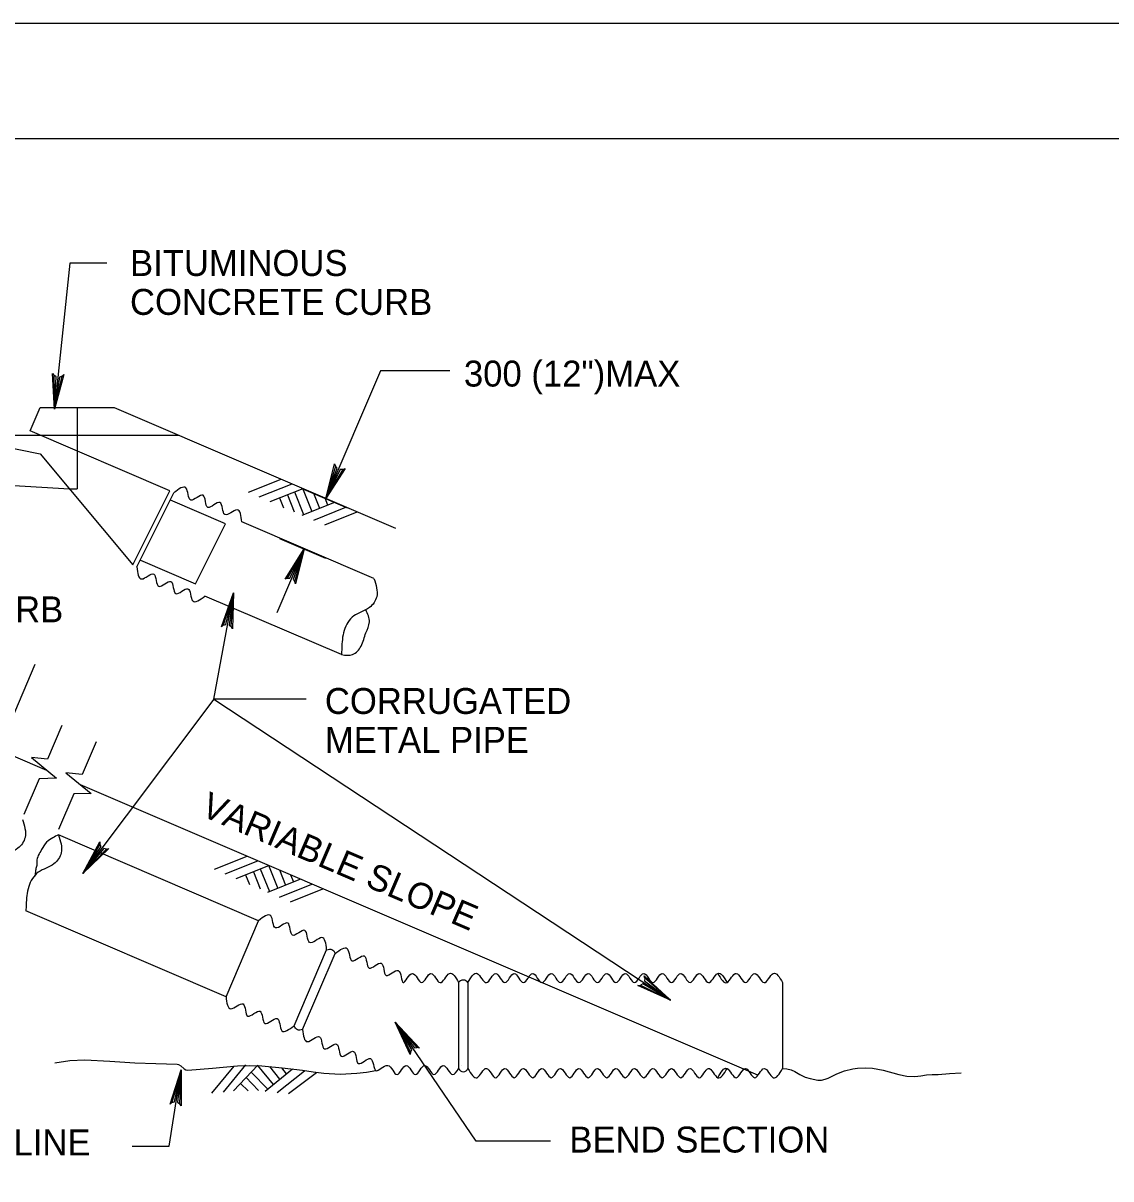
# Model space of a CAD drawing. Extents: x 637898 to 638802, y 298167 to 298761.
# Drawn here: x 638068.2 to 638209.3, y 298611.1 to 298760.9 of the extents above; entities that cross this region are included whole.
import ezdxf

# ---------------------------------------------------------------- set-up
doc = ezdxf.new("R2010")
doc.units = 0
for name, color, linetype in [('1', 7, 'Continuous'), ('2', 7, 'Continuous'), ('3', 7, 'Continuous'), ('PLT-BNDY', 7, 'Continuous')]:
    doc.layers.add(name, color=color, linetype=linetype)

msp = doc.modelspace()

# ---------------------------------------------------------------- linework, layer by layer
at = {"layer": '1'}
msp.add_lwpolyline([(638722.97, 298181.88), (638722.97, 298745.88), (637936.97, 298745.88), (637936.97, 298181.88), (638722.97, 298181.88), (638722.97, 298208.24), (638522.97, 298208.24), (638522.97, 298272.92), (638722.97, 298272.92), (638722.97, 298301.88), (638522.97, 298301.88), (638522.97, 298181.88), (638601.78, 298181.88), (638601.78, 298208.24), (638601.78, 298181.88), (638678.78, 298181.88), (638678.78, 298208.24), (638678.78, 298195.92), (638722.97, 298195.92)], dxfattribs=at)
at = {"layer": '2'}
for p, q in [((638114.56, 298715.8), (638107.47, 298699.26)), ((638069.11, 298708.04), (638070.42, 298711.08)), ((638070.42, 298711.08), (638080.02, 298711.08)), ((638075.22, 298711.08), (638075.22, 298707.48)), ((638058.42, 298707.48), (638070.42, 298705.08)), ((638087.22, 298700.28), (638069.11, 298708.04)), ((638075.22, 298707.48), (638075.22, 298700.52)), ((638070.42, 298705.08), (638082.42, 298690.68)), ((638039.61, 298702.6), (638074.22, 298700.52)), ((638097.45, 298700.08), (638101.67, 298701.76)), ((638098.83, 298699.48), (638103.08, 298701.18)), ((638074.22, 298700.52), (638075.22, 298700.52)), ((638082.42, 298690.68), (638087.22, 298700.28)), ((638082.95, 298690.41), (638087.76, 298700.01)), ((638087.76, 298700.01), (638087.76, 298700.01)), ((638100.26, 298698.87), (638104.51, 298700.57)), ((638101.46, 298699.35), (638101.97, 298698.08)), ((638102.49, 298699.76), (638103.38, 298697.54)), ((638103.4, 298700.12), (638104.57, 298697.2)), ((638104.27, 298700.63), (638110.23, 298698.08)), ((638104.44, 298700.6), (638105.64, 298697.6)), ((638105.87, 298699.98), (638106.65, 298698.03)), ((638107.32, 298699.36), (638107.69, 298698.43)), ((638089.96, 298699.07), (638089.96, 298699.07)), ((638089.96, 298699.07), (638089.96, 298699.07)), ((638092.17, 298698.12), (638092.17, 298698.12)), ((638092.17, 298698.12), (638092.17, 298698.12)), ((638104.38, 298697.11), (638108.64, 298698.81)), ((638105.89, 298696.46), (638110.08, 298698.14)), ((638094.37, 298697.18), (638094.37, 298697.18)), ((638107.32, 298695.85), (638111.51, 298697.53)), ((638096.58, 298696.23), (638096.58, 298696.23)), ((638113.71, 298688.89), (638096.58, 298696.23)), ((638098.79, 298695.29), (638098.79, 298695.29)), ((638100.99, 298694.34), (638100.99, 298694.34)), ((638101.46, 298694.1), (638107.43, 298691.54)), ((638103.2, 298693.4), (638103.2, 298693.4)), ((638105.4, 298692.45), (638105.4, 298692.45)), ((638082.95, 298690.41), (638082.95, 298690.41)), ((638107.61, 298691.51), (638107.61, 298691.51)), ((638109.82, 298690.56), (638109.82, 298690.56)), ((638112.02, 298689.62), (638112.02, 298689.62)), ((638089.57, 298687.58), (638089.57, 298687.58)), ((638091.78, 298686.63), (638091.78, 298686.63)), ((638109.49, 298679.04), (638091.78, 298686.63)), ((638093.98, 298685.69), (638093.98, 298685.69)), ((638096.19, 298684.74), (638096.19, 298684.74)), ((638098.4, 298683.8), (638098.4, 298683.8)), ((638100.6, 298682.85), (638100.6, 298682.85)), ((638102.81, 298681.91), (638102.81, 298681.91)), ((638105.02, 298680.96), (638105.02, 298680.96)), ((638107.22, 298680.02), (638107.22, 298680.02)), ((638109.43, 298679.07), (638109.43, 298679.07)), ((638069.71, 298677.75), (638065, 298666.74)), ((638073.24, 298669.86), (638071.36, 298665.47)), ((638077.67, 298667.74), (638075.85, 298663.5)), ((638070.29, 298662.96), (638068.31, 298658.34)), ((638074.78, 298660.99), (638072.79, 298656.36)), ((638098.74, 298644.56), (638072.79, 298655.69)), ((638093.03, 298651.23), (638097.25, 298652.92)), ((638094.41, 298650.64), (638098.66, 298652.33)), ((638095.84, 298650.02), (638100.08, 298651.72)), ((638100.02, 298651.75), (638101.22, 298648.75)), ((638097.05, 298650.5), (638097.55, 298649.23)), ((638098.07, 298650.91), (638098.95, 298648.69)), ((638098.97, 298651.28), (638100.15, 298648.35)), ((638099.95, 298648.26), (638104.22, 298649.97)), ((638101.45, 298651.14), (638102.23, 298649.18)), ((638102.9, 298650.52), (638103.27, 298649.59)), ((638101.46, 298647.61), (638105.66, 298649.29)), ((638102.89, 298647), (638107.09, 298648.68)), ((638094.52, 298634.71), (638068.57, 298645.84)), ((638094.52, 298634.71), (638098.74, 298644.56)), ((638103.34, 298630.93), (638107.57, 298640.78)), ((638104.45, 298630.46), (638108.67, 298640.31)), ((638108.67, 298640.31), (638108.67, 298640.31)), ((638110.88, 298639.36), (638110.88, 298639.36)), ((638113.08, 298638.42), (638113.08, 298638.42)), ((638115.29, 298637.47), (638115.29, 298637.47)), ((638117.49, 298636.53), (638117.49, 298636.53)), ((638119.89, 298636.53), (638119.89, 298636.53)), ((638122.29, 298636.53), (638122.29, 298636.53)), ((638124.69, 298636.53), (638124.69, 298636.53)), ((638124.69, 298636.53), (638124.69, 298625.41)), ((638125.89, 298636.53), (638125.89, 298625.41)), ((638125.89, 298636.53), (638125.89, 298636.53)), ((638128.29, 298636.53), (638128.29, 298636.53)), ((638130.69, 298636.53), (638130.69, 298636.53)), ((638133.09, 298636.53), (638133.09, 298636.53)), ((638133.8, 298637.27), (638163.45, 298624.57)), ((638135.49, 298636.53), (638135.49, 298636.53)), ((638137.89, 298636.53), (638137.89, 298636.53)), ((638140.29, 298636.53), (638140.29, 298636.53)), ((638142.69, 298636.53), (638142.69, 298636.53)), ((638145.09, 298636.53), (638145.09, 298636.53)), ((638147.49, 298636.53), (638147.49, 298636.53)), ((638149.89, 298636.53), (638149.89, 298636.53)), ((638152.29, 298636.53), (638152.29, 298636.53)), ((638154.69, 298636.53), (638154.69, 298636.53)), ((638157.09, 298636.53), (638157.09, 298636.53)), ((638159.49, 298636.53), (638159.49, 298636.53)), ((638159.49, 298636.53), (638159.49, 298636.53)), ((638161.89, 298636.53), (638161.89, 298636.53)), ((638164.29, 298636.53), (638164.29, 298636.53)), ((638166.69, 298636.53), (638166.69, 298636.53)), ((638166.69, 298636.53), (638166.69, 298625.41)), ((638104.45, 298630.46), (638104.45, 298630.46)), ((638106.66, 298629.51), (638106.66, 298629.51)), ((638108.86, 298628.57), (638108.86, 298628.57)), ((638111.07, 298627.62), (638111.07, 298627.62)), ((638113.27, 298626.68), (638113.27, 298626.68)), ((638092.7, 298622.19), (638095.59, 298625.7)), ((638094.19, 298622.33), (638097.1, 298625.86)), ((638095.51, 298622.51), (638098.66, 298625.82)), ((638097.79, 298624.94), (638099.97, 298622.66)), ((638098.59, 298625.81), (638100.64, 298623.31)), ((638099.58, 298622.47), (638103.14, 298625.37)), ((638100.14, 298625.66), (638101.47, 298624.03)), ((638101.15, 298622.31), (638104.7, 298625.1)), ((638101.71, 298625.5), (638102.33, 298624.71)), ((638102.62, 298622.17), (638106.24, 298624.87)), ((638115.49, 298625.81), (638115.49, 298625.81)), ((638117.9, 298625.81), (638117.9, 298625.81)), ((638120.3, 298625.81), (638120.3, 298625.81)), ((638122.7, 298625.81), (638122.7, 298625.81)), ((638125.09, 298625.81), (638125.09, 298625.81)), ((638125.89, 298625.41), (638125.89, 298625.41)), ((638128.29, 298625.41), (638128.29, 298625.41)), ((638130.69, 298625.41), (638130.69, 298625.41)), ((638133.09, 298625.41), (638133.09, 298625.41)), ((638135.49, 298625.41), (638135.49, 298625.41)), ((638137.89, 298625.41), (638137.89, 298625.41)), ((638140.29, 298625.41), (638140.29, 298625.41)), ((638142.69, 298625.41), (638142.69, 298625.41)), ((638145.09, 298625.41), (638145.09, 298625.41)), ((638147.49, 298625.41), (638147.49, 298625.41)), ((638149.89, 298625.41), (638149.89, 298625.41)), ((638152.29, 298625.41), (638152.29, 298625.41)), ((638154.69, 298625.41), (638154.69, 298625.41)), ((638157.09, 298625.41), (638157.09, 298625.41)), ((638159.49, 298625.41), (638159.49, 298625.41)), ((638159.49, 298625.41), (638159.49, 298625.41)), ((638161.89, 298625.41), (638161.89, 298625.41)), ((638164.29, 298625.41), (638164.29, 298625.41)), ((638166.69, 298625.41), (638166.69, 298625.41)), ((638096.4, 298623.45), (638097.39, 298622.5)), ((638097.08, 298624.27), (638098.74, 298622.53))]:
    msp.add_line(p, q, dxfattribs=at)
for points in [[(638079.05, 298729.76), (638074.25, 298729.76), (638072.27, 298710.86)], [(638073.27, 298715.14), (638072.94, 298715.01), (638072.27, 298710.86), (638073.27, 298715.14), (638073.48, 298715.34), (638072.27, 298710.86), (638072.5, 298715.05), (638072.21, 298715.24), (638072.27, 298710.86), (638072.03, 298715.49), (638072.21, 298715.24)], [(638123.56, 298715.8), (638114.56, 298715.8)], [(638080.01, 298711.07), (638116.51, 298695.42)], [(638058.42, 298707.48), (638075.21, 298707.48)], [(638075.21, 298707.48), (638088.37, 298707.48)], [(638109.7, 298703.05), (638109.34, 298703.02), (638107.47, 298699.26), (638109.7, 298703.05), (638109.96, 298703.18), (638107.47, 298699.26), (638108.94, 298703.19), (638108.71, 298703.46), (638107.47, 298699.26), (638108.61, 298703.76), (638108.71, 298703.46)], [(638083.44, 298691.29), (638090.58, 298688.23), (638094.47, 298696), (638087.33, 298699.07)], [(638104.67, 298692.73), (638101.13, 298684.46)], [(638102.45, 298688.94), (638102.8, 298688.96), (638104.67, 298692.73), (638102.45, 298688.94), (638102.19, 298688.81), (638104.67, 298692.73), (638103.21, 298688.79), (638103.43, 298688.53), (638104.67, 298692.73), (638103.53, 298688.23), (638103.43, 298688.53)], [(638092.93, 298673.27), (638095.48, 298687.03)], [(638094.15, 298682.85), (638094.49, 298682.95), (638095.48, 298687.03), (638094.15, 298682.85), (638093.92, 298682.66), (638095.48, 298687.03), (638094.92, 298682.87), (638095.2, 298682.67), (638095.48, 298687.03), (638095.36, 298682.4), (638095.2, 298682.67)], [(638034.41, 298679.87), (638071.24, 298664.08)], [(638104.93, 298673.27), (638100.13, 298673.27), (638092.93, 298673.27), (638075.97, 298650.68)], [(638092.93, 298673.27), (638152.17, 298634.25)], [(638071.36, 298665.47), (638069.28, 298665.69), (638072.55, 298663.01), (638070.29, 298662.96)], [(638075.85, 298663.5), (638073.77, 298663.72), (638077.04, 298661.04), (638074.78, 298660.99)], [(638075.59, 298662.22), (638133.8, 298637.27)], [(638079.03, 298653.84), (638078.68, 298653.9), (638075.97, 298650.68), (638079.03, 298653.84), (638079.31, 298653.9), (638075.97, 298650.68), (638078.32, 298654.16), (638078.16, 298654.47), (638075.97, 298650.68), (638078.14, 298654.78), (638078.16, 298654.47)], [(638148.83, 298637.1), (638148.79, 298636.75), (638152.17, 298634.25), (638148.83, 298637.1), (638148.75, 298637.39), (638152.17, 298634.25), (638148.56, 298636.38), (638148.26, 298636.21), (638152.17, 298634.25), (638147.94, 298636.16), (638148.26, 298636.21)], [(638136.58, 298615.97), (638131.78, 298615.97), (638126.98, 298615.97), (638116.44, 298631.42)], [(638118.44, 298627.52), (638118.61, 298627.83), (638116.44, 298631.42), (638118.44, 298627.52), (638118.41, 298627.22), (638116.44, 298631.42), (638118.97, 298628.08), (638119.32, 298628.13), (638116.44, 298631.42), (638119.62, 298628.05), (638119.32, 298628.13)], [(638072.32, 298626.15), (638074.28, 298626.45), (638076.23, 298626.54), (638079.47, 298626.36), (638082.7, 298626.15), (638085.44, 298626.05), (638088.19, 298625.95), (638088.37, 298625.91), (638088.67, 298625.73), (638089.09, 298625.36), (638089.32, 298625.22), (638089.56, 298625.17), (638092.78, 298625.45), (638096.02, 298625.76), (638097.59, 298625.79), (638099.16, 298625.76), (638101.81, 298625.49), (638104.45, 298625.17), (638105.82, 298624.97), (638107.19, 298624.78), (638109.34, 298624.67), (638111.5, 298624.78), (638112.73, 298624.91), (638113.95, 298625.13)], [(638082.34, 298615.35), (638087.14, 298615.35), (638088.7, 298625.21)], [(638087.48, 298620.99), (638087.82, 298621.1), (638088.7, 298625.21), (638087.48, 298620.99), (638087.26, 298620.8), (638088.7, 298625.21), (638088.25, 298621.04), (638088.54, 298620.84), (638088.7, 298625.21), (638088.7, 298620.57), (638088.54, 298620.84)], [(638166.69, 298625.41), (638167.24, 298625.35), (638167.79, 298625.22), (638168.27, 298625.01), (638168.95, 298624.63), (638169.64, 298624.29), (638170.28, 298624.09), (638171.26, 298623.91), (638171.75, 298623.91), (638172.21, 298624), (638172.59, 298624.15), (638173.71, 298624.72), (638174.74, 298625.08), (638175.79, 298625.36), (638176.43, 298625.45), (638177.4, 298625.48), (638178.36, 298625.43), (638179.73, 298625.2), (638181.79, 298624.63), (638182.83, 298624.42), (638183.86, 298624.36), (638184.61, 298624.46), (638185.36, 298624.57), (638186.11, 298624.61), (638186.86, 298624.64), (638188.36, 298624.74), (638189.86, 298624.86)]]:
    msp.add_lwpolyline(points, dxfattribs=at)
for centre, radius, start, end in [((638125.29, 298636.17), 0.698, 30.7717, 149.2283), ((638125.29, 298625.61), 0.633, 198.7071, 341.2929)]:
    msp.add_arc(centre, radius, start, end, dxfattribs=at)
for points in [[(638096.58, 298696.23), (638095.95, 298697.81), (638094.37, 298697.18), (638093.74, 298698.75), (638092.17, 298698.12), (638091.54, 298699.7), (638089.96, 298699.07), (638089.33, 298700.65), (638087.76, 298700.01)], [(638082.95, 298690.41), (638083.58, 298688.84), (638085.16, 298689.47), (638085.79, 298687.89), (638087.37, 298688.52), (638088, 298686.95), (638089.57, 298687.58), (638090.2, 298686), (638091.78, 298686.63)], [(638113.71, 298688.89), (638114.06, 298686.55), (638113.12, 298685.14), (638111.09, 298684.05), (638109.84, 298682.17), (638109.53, 298679.83), (638109.49, 298679.04)], [(638109.49, 298679.04), (638110.94, 298679.05), (638112.03, 298680.14), (638112.66, 298681.86), (638113.12, 298683.27), (638112.66, 298684.83)], [(638068.11, 298657.69), (638068.46, 298655.35), (638067.53, 298653.94), (638065.49, 298652.85), (638064.24, 298650.97), (638063.93, 298648.63), (638063.89, 298647.84)], [(638072.79, 298655.69), (638073.15, 298653.34), (638072.21, 298651.93), (638070.18, 298650.84), (638068.93, 298648.97), (638068.61, 298646.62), (638068.57, 298645.84)], [(638072.79, 298655.69), (638072.05, 298655.29), (638071.26, 298654.73), (638070.6, 298653.77), (638070.18, 298653.01), (638069.98, 298652.22), (638069.98, 298651.73), (638069.84, 298651.2), (638069.78, 298650.57), (638069.75, 298650.31)], [(638107.57, 298640.78), (638106.94, 298642.36), (638105.36, 298641.73), (638104.73, 298643.3), (638103.16, 298642.67), (638102.53, 298644.25), (638100.95, 298643.62), (638100.32, 298645.19), (638098.74, 298644.56)], [(638108.67, 298640.31), (638110.24, 298640.94), (638110.88, 298639.36), (638112.45, 298639.99), (638113.08, 298638.42), (638114.66, 298639.05), (638115.29, 298637.47), (638116.86, 298638.1), (638117.49, 298636.53), (638118.69, 298637.73), (638119.89, 298636.53), (638121.09, 298637.73), (638122.29, 298636.53), (638123.49, 298637.73), (638124.69, 298636.53)], [(638107.57, 298640.78), (638108.25, 298640.84), (638108.67, 298640.31)], [(638125.89, 298636.53), (638127.09, 298637.73), (638128.29, 298636.53), (638129.49, 298637.73), (638130.69, 298636.53), (638131.89, 298637.73), (638133.09, 298636.53), (638134.29, 298637.73), (638135.49, 298636.53), (638136.69, 298637.73), (638137.89, 298636.53), (638139.09, 298637.73), (638140.29, 298636.53), (638141.49, 298637.73), (638142.69, 298636.53), (638143.89, 298637.73), (638145.09, 298636.53), (638146.29, 298637.73), (638147.49, 298636.53), (638148.69, 298637.73), (638149.89, 298636.53), (638151.09, 298637.73), (638152.29, 298636.53), (638153.49, 298637.73), (638154.69, 298636.53), (638155.89, 298637.73), (638157.09, 298636.53), (638158.29, 298637.73), (638159.49, 298636.53)], [(638158.29, 298637.73), (638159.49, 298636.53), (638160.69, 298637.73), (638161.89, 298636.53), (638163.09, 298637.73), (638164.29, 298636.53), (638165.49, 298637.73), (638166.69, 298636.53)], [(638094.52, 298634.71), (638095.15, 298633.14), (638096.73, 298633.77), (638097.36, 298632.19), (638098.93, 298632.82), (638099.56, 298631.25), (638101.14, 298631.88), (638101.77, 298630.3), (638103.34, 298630.93)], [(638104.45, 298630.46), (638103.77, 298630.4), (638103.34, 298630.93)], [(638104.45, 298630.46), (638105.08, 298628.88), (638106.66, 298629.51), (638107.29, 298627.94), (638108.86, 298628.57), (638109.49, 298626.99), (638111.07, 298627.62), (638111.7, 298626.05), (638113.27, 298626.68), (638113.95, 298625.13), (638115.49, 298625.81), (638116.7, 298624.61), (638117.9, 298625.81), (638119.09, 298624.61), (638120.3, 298625.81), (638121.49, 298624.61), (638122.7, 298625.81), (638123.9, 298624.61), (638124.67, 298625.39)], [(638125.89, 298625.41), (638127.09, 298624.21), (638128.29, 298625.41), (638129.49, 298624.21), (638130.69, 298625.41), (638131.89, 298624.21), (638133.09, 298625.41), (638134.29, 298624.21), (638135.49, 298625.41), (638136.69, 298624.21), (638137.89, 298625.41), (638139.09, 298624.21), (638140.29, 298625.41), (638141.49, 298624.21), (638142.69, 298625.41), (638143.89, 298624.21), (638145.09, 298625.41), (638146.29, 298624.21), (638147.49, 298625.41), (638148.69, 298624.21), (638149.89, 298625.41), (638151.09, 298624.21), (638152.29, 298625.41), (638153.49, 298624.21), (638154.69, 298625.41), (638155.89, 298624.21), (638157.09, 298625.41), (638158.29, 298624.21), (638159.49, 298625.41)], [(638158.29, 298624.21), (638159.49, 298625.41), (638160.69, 298624.21), (638161.89, 298625.41), (638163.09, 298624.21), (638164.29, 298625.41), (638165.49, 298624.21), (638166.69, 298625.41)]]:
    msp.add_spline(points, degree=3, dxfattribs=at)
at = {"layer": 'PLT-BNDY'}
msp.add_lwpolyline([(637897.97, 298760.88), (638738.97, 298760.88), (638738.97, 298166.88), (637897.97, 298166.88)], close=True, dxfattribs=at)

# ---------------------------------------------------------------- texts
at = {"layer": '3'}
for s, p in [('BITUMINOUS', (638082.07, 298728.11)), ('CONCRETE CURB', (638082.07, 298723.07)), ('300 (12")MAX', (638125.37, 298713.78)), ('CONCRETE CURB', (638034.22, 298683.23)), ('CORRUGATED', (638107.34, 298671.35)), ('METAL PIPE', (638107.34, 298666.31)), ('GROUND LINE', (638045.75, 298614.14)), ('BEND SECTION', (638139.05, 298614.51))]:
    msp.add_text(s, height=3.36, dxfattribs=at).set_placement(p)
msp.add_text('VARIABLE SLOPE', height=3.36, rotation=336.8014, dxfattribs=at).set_placement((638091.08, 298658.24))

doc.saveas('drawing.dxf')
